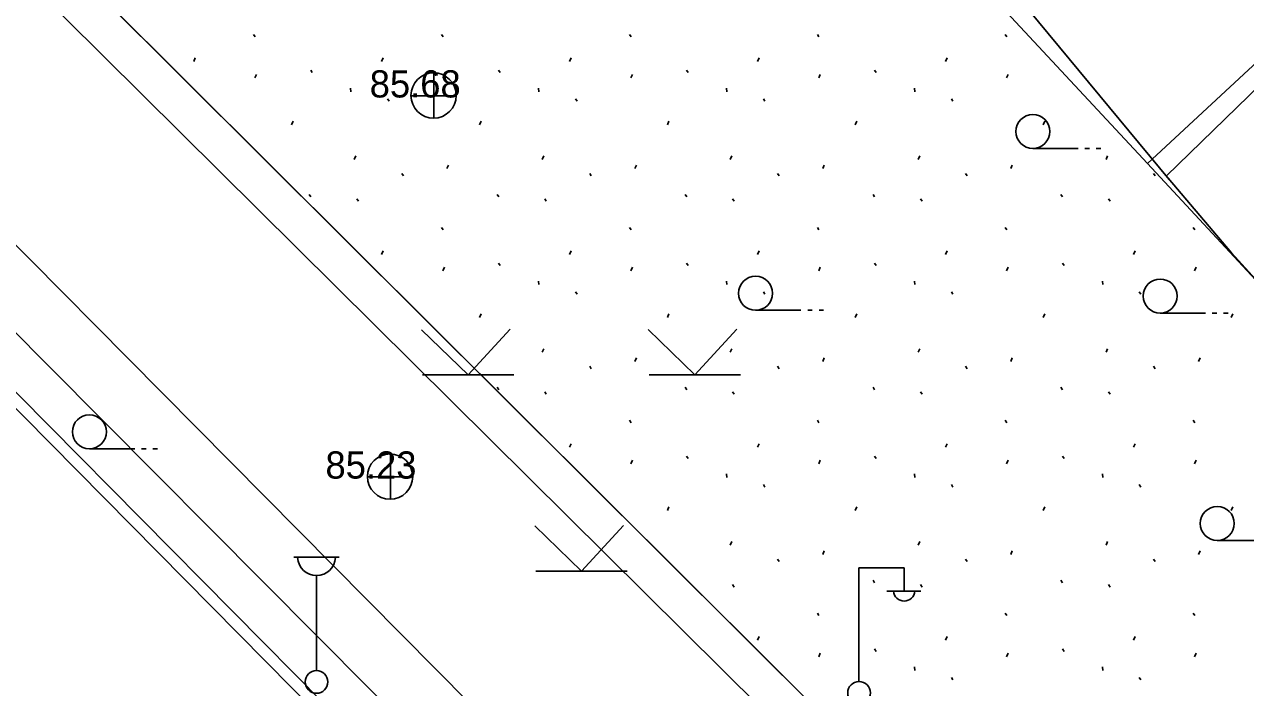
# Model space of a CAD drawing. Extents: x 412225 to 413380, y 4456471 to 4457189.
# Drawn here: x 412465.4 to 412519.2, y 4456938.5 to 4456967.8 of the extents above; entities that cross this region are included whole.
import ezdxf

# ---------------------------------------------------------------- set-up
doc = ezdxf.new("R2010")
doc.units = 0
for name, color, linetype in [('0_HALİHAZIR', 7, 'Continuous'), ('0_KADASTRO', 7, 'Continuous'), ('Level 27', 7, 'Continuous'), ('Level 41', 7, 'Continuous'), ('Level 57', 7, 'Continuous'), ('Level 62', 7, 'Continuous'), ('Level 8', 7, 'Continuous')]:
    doc.layers.add(name, color=color, linetype=linetype)

msp = doc.modelspace()

# ---------------------------------------------------------------- linework, layer by layer
at = {"layer": '0_HALİHAZIR'}
for p, q in [((412483.432, 4456963.625), (412483.432, 4456965.625)), ((412482.412, 4456964.615), (412484.412, 4456964.615)), ((412509.857, 4456962.296), (412511.857, 4456962.296)), ((412512.157, 4456962.296), (412512.357, 4456962.296)), ((412512.657, 4456962.296), (412512.857, 4456962.296)), ((412497.624, 4456955.157), (412499.624, 4456955.158)), ((412499.924, 4456955.158), (412500.124, 4456955.158)), ((412500.424, 4456955.158), (412500.624, 4456955.158)), ((412515.475, 4456955.038), (412517.475, 4456955.038)), ((412517.775, 4456955.038), (412517.975, 4456955.038)), ((412518.275, 4456955.038), (412518.475, 4456955.038)), ((412484.942, 4456952.313), (412482.882, 4456954.303)), ((412484.942, 4456952.313), (412486.792, 4456954.324)), ((412494.943, 4456952.314), (412492.882, 4456954.304)), ((412494.943, 4456952.314), (412496.792, 4456954.324)), ((412482.922, 4456952.313), (412486.962, 4456952.314)), ((412492.923, 4456952.314), (412496.963, 4456952.314)), ((412468.227, 4456949.049), (412470.227, 4456949.049)), ((412470.527, 4456949.049), (412470.727, 4456949.049)), ((412471.027, 4456949.049), (412471.227, 4456949.049)), ((412481.508, 4456946.815), (412481.508, 4456948.815)), ((412480.488, 4456947.805), (412482.488, 4456947.805)), ((412489.943, 4456943.654), (412487.883, 4456945.644)), ((412489.943, 4456943.654), (412491.793, 4456945.664)), ((412517.995, 4456945.005), (412519.995, 4456945.005)), ((412477.25, 4456944.265), (412479.25, 4456944.265)), ((412478.25, 4456939.265), (412478.25, 4456943.458)), ((412487.923, 4456943.654), (412491.963, 4456943.654)), ((412502.176, 4456938.805), (412502.176, 4456943.805)), ((412502.176, 4456943.805), (412504.176, 4456943.805)), ((412504.176, 4456942.805), (412504.176, 4456943.805)), ((412503.416, 4456942.765), (412504.916, 4456942.765))]:
    msp.add_line(p, q, dxfattribs=at)
for points in [[(412515.866, 4456960.932), (412501.288, 4456978.539), (412536.879, 4457008.77), (412550.404, 4456993.29)], [(412513.116, 4456909.938), (412497.081, 4456925.639), (412469.945, 4456953.037), (412435.441, 4456987.862), (412419.372, 4457004.721)], [(412417.321, 4457002.244), (412443.331, 4456975.989), (412466.46, 4456952.659), (412490.035, 4456928.962), (412506.529, 4456912.027), (412510.582, 4456907.986)], [(412553.419, 4456989.855), (412564.734, 4456978.225), (412568.348, 4456974.246), (412544.691, 4456953.408), (412533.004, 4456941.924), (412518.623, 4456957.688), (412515.821, 4456960.985)], [(412433.199, 4456983.611), (412458.357, 4456958.224), (412478.594, 4456937.778), (412494.707, 4456921.709), (412506.6, 4456909.868), (412508.244, 4456908.725), (412509.715, 4456908.155), (412510.968, 4456907.91), (412512.709, 4456907.952), (412514.827, 4456908.164), (412517.02, 4456908.788), (412521.642, 4456910.812), (412528.714, 4456914.991), (412542.04, 4456923.109), (412563.128, 4456935.466), (412569.855, 4456939.641), (412584.556, 4456948.006), (412584.762, 4456948.165)], [(412525.111, 4456970.194), (412515.744, 4456961.08)]]:
    msp.add_lwpolyline(points, dxfattribs=at)
for centre, radius in [((412483.416, 4456964.633), 1), ((412509.857, 4456963.046), 0.75), ((412497.624, 4456955.907), 0.75), ((412515.475, 4456955.788), 0.75), ((412468.227, 4456949.799), 0.75), ((412481.493, 4456947.823), 1), ((412517.995, 4456945.755), 0.75), ((412478.25, 4456938.765), 0.5), ((412502.187, 4456938.28), 0.5)]:
    msp.add_circle(centre, radius, dxfattribs=at)
for centre, radius, start, end in [((412478.25, 4456944.295), 0.837, 183.298, 356.9072), ((412504.177, 4456942.808), 0.474, 184.8384, 355.1464)]:
    msp.add_arc(centre, radius, start, end, dxfattribs=at)
at = {"layer": '0_KADASTRO'}
for points in [[(412531.386, 4456906.626), (412255.662, 4457181.172)], [(412521.644, 4456995.155), (412501.285, 4456976.281), (412514.918, 4456961.632), (412519.687, 4456956.508)]]:
    msp.add_lwpolyline(points, dxfattribs=at)
msp.add_lwpolyline([(412501.285, 4456976.281), (412521.644, 4456995.155), (412536.485, 4457008.915), (412550.11, 4456994.275), (412514.918, 4456961.632)], close=True, dxfattribs=at)
at = {"layer": 'Level 27'}
msp.add_line((412531.386, 4456906.626), (412255.662, 4457181.172), dxfattribs=at)
msp.add_lwpolyline([(412550.11, 4456994.275), (412514.918, 4456961.632), (412519.687, 4456956.508), (412554.879, 4456989.15)], dxfattribs=at)
at = {"layer": 'Level 41'}
for p, q in [((412475.47, 4456967.327), (412475.541, 4456967.22)), ((412483.763, 4456967.327), (412483.834, 4456967.22)), ((412492.056, 4456967.327), (412492.127, 4456967.22)), ((412500.349, 4456967.327), (412500.42, 4456967.22)), ((412508.642, 4456967.327), (412508.713, 4456967.22)), ((412472.829, 4456966.134), (412472.9, 4456966.293)), ((412481.122, 4456966.134), (412481.193, 4456966.293)), ((412489.415, 4456966.134), (412489.486, 4456966.293)), ((412497.708, 4456966.134), (412497.779, 4456966.293)), ((412506.001, 4456966.134), (412506.072, 4456966.293)), ((412475.528, 4456965.405), (412475.6, 4456965.565)), ((412477.993, 4456965.75), (412478.064, 4456965.643)), ((412483.821, 4456965.405), (412483.893, 4456965.565)), ((412486.286, 4456965.75), (412486.357, 4456965.643)), ((412492.114, 4456965.405), (412492.186, 4456965.565)), ((412494.579, 4456965.75), (412494.65, 4456965.643)), ((412500.407, 4456965.405), (412500.479, 4456965.565)), ((412502.872, 4456965.75), (412502.943, 4456965.643)), ((412508.7, 4456965.405), (412508.772, 4456965.565)), ((412479.751, 4456964.959), (412479.769, 4456964.799)), ((412488.044, 4456964.959), (412488.062, 4456964.799)), ((412496.337, 4456964.959), (412496.355, 4456964.799)), ((412504.63, 4456964.959), (412504.648, 4456964.799)), ((412481.381, 4456964.489), (412481.451, 4456964.382)), ((412489.674, 4456964.489), (412489.744, 4456964.382)), ((412497.967, 4456964.489), (412498.037, 4456964.382)), ((412506.26, 4456964.489), (412506.33, 4456964.382)), ((412477.144, 4456963.345), (412477.216, 4456963.505)), ((412485.437, 4456963.345), (412485.509, 4456963.505)), ((412493.73, 4456963.345), (412493.802, 4456963.505)), ((412502.023, 4456963.345), (412502.095, 4456963.505)), ((412510.316, 4456963.345), (412510.388, 4456963.505)), ((412479.916, 4456961.815), (412479.986, 4456961.975)), ((412488.209, 4456961.815), (412488.279, 4456961.975)), ((412496.502, 4456961.815), (412496.572, 4456961.975)), ((412504.795, 4456961.815), (412504.865, 4456961.975)), ((412513.088, 4456961.815), (412513.158, 4456961.975)), ((412482.011, 4456961.199), (412482.082, 4456961.093)), ((412483.999, 4456961.407), (412484.07, 4456961.567)), ((412490.304, 4456961.199), (412490.375, 4456961.093)), ((412492.292, 4456961.407), (412492.363, 4456961.567)), ((412498.597, 4456961.199), (412498.668, 4456961.093)), ((412500.585, 4456961.407), (412500.656, 4456961.567)), ((412506.89, 4456961.199), (412506.961, 4456961.093)), ((412508.878, 4456961.407), (412508.949, 4456961.567)), ((412515.183, 4456961.199), (412515.254, 4456961.093)), ((412477.926, 4456960.27), (412477.997, 4456960.163)), ((412480.025, 4456960.078), (412480.096, 4456959.971)), ((412486.219, 4456960.27), (412486.29, 4456960.163)), ((412488.318, 4456960.078), (412488.389, 4456959.971)), ((412494.512, 4456960.27), (412494.583, 4456960.163)), ((412496.611, 4456960.078), (412496.682, 4456959.971)), ((412502.805, 4456960.27), (412502.876, 4456960.163)), ((412504.904, 4456960.078), (412504.975, 4456959.971)), ((412511.098, 4456960.27), (412511.169, 4456960.163)), ((412513.197, 4456960.078), (412513.268, 4456959.971)), ((412483.763, 4456958.817), (412483.834, 4456958.71)), ((412492.056, 4456958.817), (412492.127, 4456958.71)), ((412500.349, 4456958.817), (412500.42, 4456958.71)), ((412508.642, 4456958.817), (412508.713, 4456958.71)), ((412516.935, 4456958.817), (412517.006, 4456958.71)), ((412481.122, 4456957.624), (412481.193, 4456957.783)), ((412489.415, 4456957.624), (412489.486, 4456957.783)), ((412497.708, 4456957.624), (412497.779, 4456957.783)), ((412506.001, 4456957.624), (412506.072, 4456957.783)), ((412514.294, 4456957.624), (412514.365, 4456957.783)), ((412483.821, 4456956.895), (412483.893, 4456957.055)), ((412486.286, 4456957.24), (412486.357, 4456957.133)), ((412492.114, 4456956.895), (412492.186, 4456957.055)), ((412494.579, 4456957.24), (412494.65, 4456957.133)), ((412500.407, 4456956.895), (412500.479, 4456957.055)), ((412502.872, 4456957.24), (412502.943, 4456957.133)), ((412508.7, 4456956.895), (412508.772, 4456957.055)), ((412511.165, 4456957.24), (412511.236, 4456957.133)), ((412516.993, 4456956.895), (412517.065, 4456957.055)), ((412488.044, 4456956.449), (412488.062, 4456956.289)), ((412496.337, 4456956.449), (412496.355, 4456956.289)), ((412504.63, 4456956.449), (412504.648, 4456956.289)), ((412512.923, 4456956.449), (412512.941, 4456956.289)), ((412489.674, 4456955.979), (412489.744, 4456955.872)), ((412497.967, 4456955.979), (412498.037, 4456955.872)), ((412506.26, 4456955.979), (412506.33, 4456955.872)), ((412514.553, 4456955.979), (412514.623, 4456955.872)), ((412485.437, 4456954.835), (412485.509, 4456954.995)), ((412493.73, 4456954.835), (412493.802, 4456954.995)), ((412502.023, 4456954.835), (412502.095, 4456954.995)), ((412510.316, 4456954.835), (412510.388, 4456954.995)), ((412518.609, 4456954.835), (412518.681, 4456954.995)), ((412488.209, 4456953.305), (412488.279, 4456953.465)), ((412492.292, 4456952.897), (412492.363, 4456953.057)), ((412496.502, 4456953.305), (412496.572, 4456953.465)), ((412500.585, 4456952.897), (412500.656, 4456953.057)), ((412504.795, 4456953.305), (412504.865, 4456953.465)), ((412508.878, 4456952.897), (412508.949, 4456953.057)), ((412513.088, 4456953.305), (412513.158, 4456953.465)), ((412517.171, 4456952.897), (412517.242, 4456953.057)), ((412490.304, 4456952.689), (412490.375, 4456952.583)), ((412498.597, 4456952.689), (412498.668, 4456952.583)), ((412506.89, 4456952.689), (412506.961, 4456952.583)), ((412515.183, 4456952.689), (412515.254, 4456952.583)), ((412486.219, 4456951.76), (412486.29, 4456951.653)), ((412488.318, 4456951.568), (412488.389, 4456951.461)), ((412494.512, 4456951.76), (412494.583, 4456951.653)), ((412496.611, 4456951.568), (412496.682, 4456951.461)), ((412502.805, 4456951.76), (412502.876, 4456951.653)), ((412504.904, 4456951.568), (412504.975, 4456951.461)), ((412511.098, 4456951.76), (412511.169, 4456951.653)), ((412513.197, 4456951.568), (412513.268, 4456951.461)), ((412492.056, 4456950.307), (412492.127, 4456950.2)), ((412500.349, 4456950.307), (412500.42, 4456950.2)), ((412508.642, 4456950.307), (412508.713, 4456950.2)), ((412516.935, 4456950.307), (412517.006, 4456950.2)), ((412489.415, 4456949.114), (412489.486, 4456949.273)), ((412497.708, 4456949.114), (412497.779, 4456949.273)), ((412506.001, 4456949.114), (412506.072, 4456949.273)), ((412514.294, 4456949.114), (412514.365, 4456949.273)), ((412494.579, 4456948.73), (412494.65, 4456948.623)), ((412502.872, 4456948.73), (412502.943, 4456948.623)), ((412511.165, 4456948.73), (412511.236, 4456948.623)), ((412492.114, 4456948.385), (412492.186, 4456948.545)), ((412500.407, 4456948.385), (412500.479, 4456948.545)), ((412508.7, 4456948.385), (412508.772, 4456948.545)), ((412516.993, 4456948.385), (412517.065, 4456948.545)), ((412496.337, 4456947.939), (412496.355, 4456947.779)), ((412504.63, 4456947.939), (412504.648, 4456947.779)), ((412512.923, 4456947.939), (412512.941, 4456947.779)), ((412497.967, 4456947.469), (412498.037, 4456947.362)), ((412506.26, 4456947.469), (412506.33, 4456947.362)), ((412514.553, 4456947.469), (412514.623, 4456947.362)), ((412493.73, 4456946.325), (412493.802, 4456946.485)), ((412502.023, 4456946.325), (412502.095, 4456946.485)), ((412510.316, 4456946.325), (412510.388, 4456946.485)), ((412518.609, 4456946.325), (412518.681, 4456946.485)), ((412496.502, 4456944.795), (412496.572, 4456944.955)), ((412504.795, 4456944.795), (412504.865, 4456944.955)), ((412513.088, 4456944.795), (412513.158, 4456944.955)), ((412500.585, 4456944.387), (412500.656, 4456944.547)), ((412508.878, 4456944.387), (412508.949, 4456944.547)), ((412517.171, 4456944.387), (412517.242, 4456944.547)), ((412498.597, 4456944.179), (412498.668, 4456944.073)), ((412506.89, 4456944.179), (412506.961, 4456944.073)), ((412515.183, 4456944.179), (412515.254, 4456944.073)), ((412496.611, 4456943.058), (412496.682, 4456942.951)), ((412502.805, 4456943.25), (412502.876, 4456943.143)), ((412504.904, 4456943.058), (412504.975, 4456942.951)), ((412511.098, 4456943.25), (412511.169, 4456943.143)), ((412513.197, 4456943.058), (412513.268, 4456942.951)), ((412500.349, 4456941.797), (412500.42, 4456941.69)), ((412508.642, 4456941.797), (412508.713, 4456941.69)), ((412516.935, 4456941.797), (412517.006, 4456941.69)), ((412497.708, 4456940.604), (412497.779, 4456940.763)), ((412506.001, 4456940.604), (412506.072, 4456940.763)), ((412514.294, 4456940.604), (412514.365, 4456940.763)), ((412502.872, 4456940.22), (412502.943, 4456940.113)), ((412511.165, 4456940.22), (412511.236, 4456940.113)), ((412500.407, 4456939.875), (412500.479, 4456940.035)), ((412508.7, 4456939.875), (412508.772, 4456940.035)), ((412516.993, 4456939.875), (412517.065, 4456940.035)), ((412504.63, 4456939.429), (412504.648, 4456939.269)), ((412512.923, 4456939.429), (412512.941, 4456939.269)), ((412506.26, 4456938.959), (412506.33, 4456938.852)), ((412514.553, 4456938.959), (412514.623, 4456938.852))]:
    msp.add_line(p, q, dxfattribs=at)
at = {"layer": 'Level 57'}
msp.add_lwpolyline([(412514.918, 4456961.632), (412501.285, 4456976.281), (412521.644, 4456995.155), (412536.485, 4457008.915)], dxfattribs=at)
at = {"layer": 'Level 62'}
msp.add_line((412393.43, 4457023.16), (412517.28, 4456897.96), dxfattribs=at)
at = {"layer": 'Level 8'}
msp.add_lwpolyline([(412706.1, 4457175.965), (412751.217, 4457041.463), (412764.575, 4457001.385), (412790.361, 4457003.87), (412821.118, 4456953.851), (412699.954, 4456860.338), (412631.485, 4456804.219), (412585.777, 4456849.927), (412523.439, 4456912.266), (412460.309, 4456974.831), (412403.512, 4457031.625), (412342.192, 4457092.946), (412287.774, 4457146.913), (412253.259, 4457181.199)], dxfattribs=at)

# ---------------------------------------------------------------- texts
at = {"layer": '0_HALİHAZIR'}
for s, p in [('85.68', (412480.595, 4456964.545)), ('85.23', (412478.644, 4456947.735))]:
    msp.add_text(s, height=1.2, dxfattribs=at).set_placement(p)

doc.saveas('drawing.dxf')
